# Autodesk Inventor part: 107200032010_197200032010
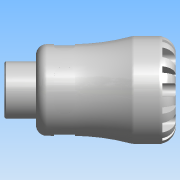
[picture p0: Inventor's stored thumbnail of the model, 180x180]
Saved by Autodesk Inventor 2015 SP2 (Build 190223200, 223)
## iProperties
Created: 2016-12
Part Number: 107200032010_197200032010
Material: PVC-Piping
Description: PLASSON MALE INTEGRAL BRASS THREAD 32X1" SERIES 1
Document SubType Name: Modeling
Designer: KIM
Mass: 61.7504 g
Surface Area: 140.097 cm^2
Volume: 44.1074 cm^3
Density: 1.4 g/cm^3
Appearance: Smooth - White
Author: KIM
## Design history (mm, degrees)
derived "1072.ipt"
feature "Solid1::1072.ipt"
tag "TaggingFeature1"
body "Solid1"
other parameters: "d0" = 92, "d1" = 23.1, "d2" = 32, "d4" = 58, "d6" = 55, "d8" = 49.3, "d13" = 7.2, "d14" = 7.2, "d15" = 0, "d17" = 360 deg, "d19" = 8 deg, "d20" = 0.64, "d21" = 0.64, "d22" = 8 deg, "d24" = 0, "d26" = 360 deg, "d32" = 5.8, "d33" = 5.8, "d34" = 30.931, "d38" = 17, "d39" = 0.92793, "d42" = 11.2, "d43" = 7.36, "d45" = 14.112, "d46" = 0, "d59" = 360 deg, "d61" = 9.52, "d62" = 0.64, "d64" = 0, "d65" = 0.58, "d68" = 4.57143, "d_" = 32, "E_" = 58, "H_" = 92, "l_" = 55, "R_" = 30.931, "l_2" = 17, "d9" = 9, "d11" = 58
